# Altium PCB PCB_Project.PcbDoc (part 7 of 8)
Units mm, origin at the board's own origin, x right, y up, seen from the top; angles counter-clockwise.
Board outline 250 x 200 mm, 6 copper layers (Top Shielding/Sig, Sig 1, PWR, GND, Sig 4, Bottom Shielding/Sig), stack 1.568 mm thick; 736 components, 420 nets, 1929 pads, 2185 vias.
Unrouted connection lines stored in the file: 47.
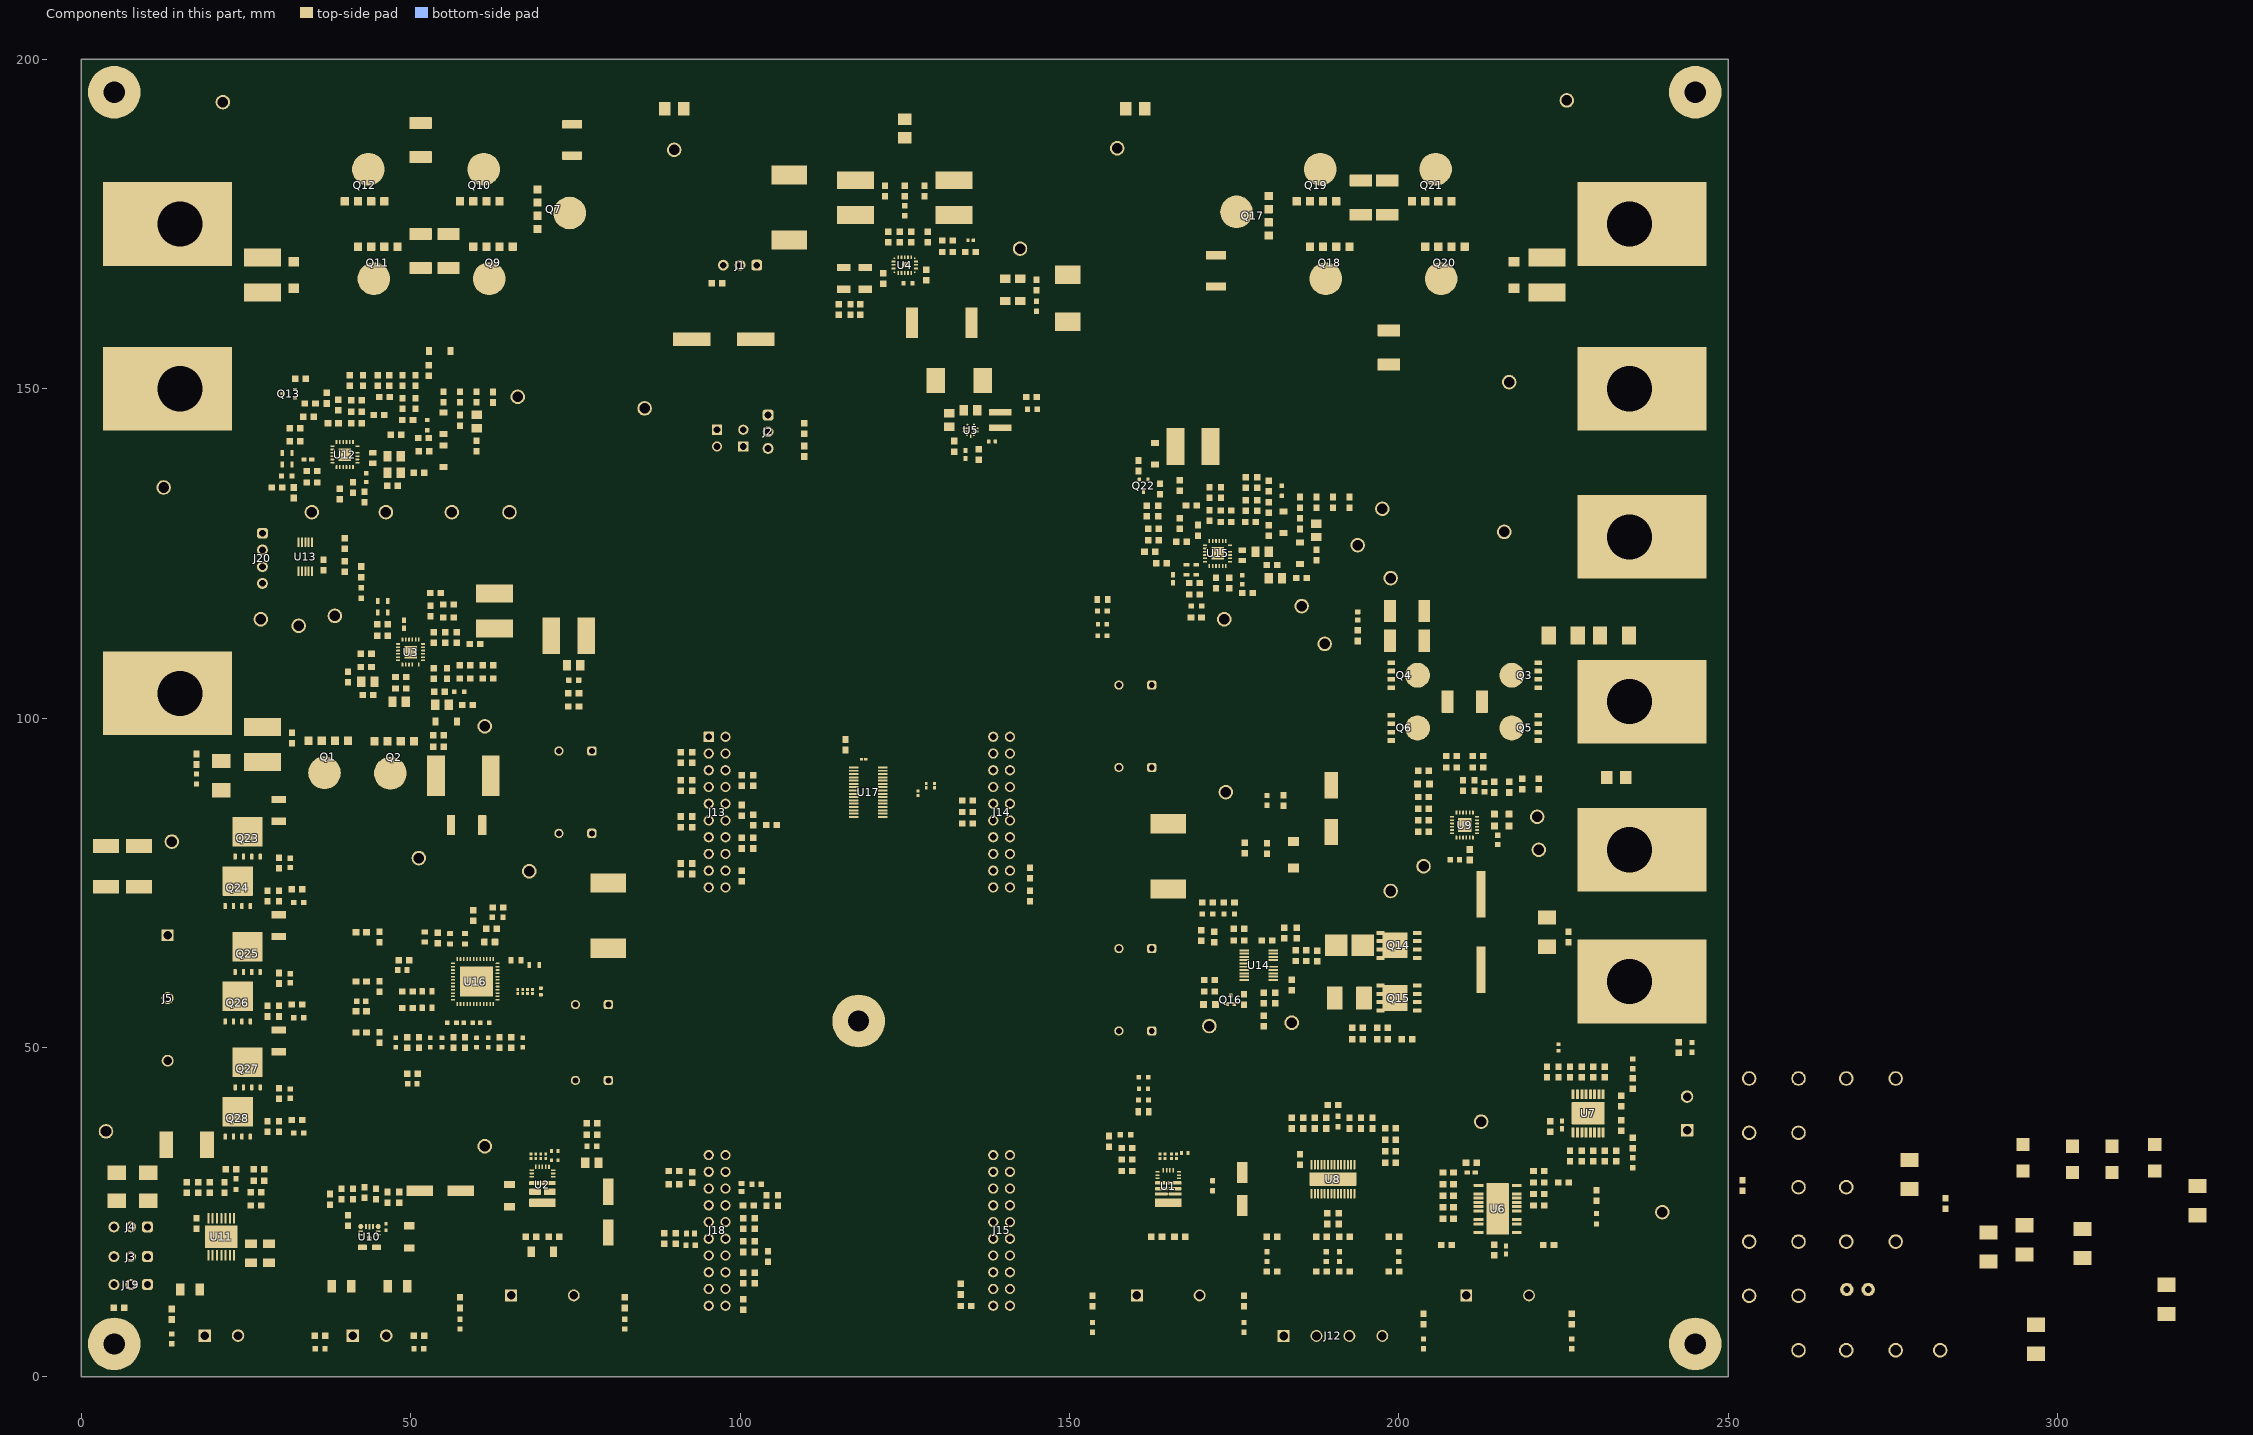
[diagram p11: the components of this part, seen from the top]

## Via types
v1: diameter 0.635, hole 0.254, Top Shielding/Sig to Bottom Shielding/Sig, tented both sides, 778 vias
v2: diameter 0.6, hole 0.254, Top Shielding/Sig to Bottom Shielding/Sig, tented both sides, 726 vias
v3: diameter 0.813, hole 0.406, Top Shielding/Sig to Bottom Shielding/Sig, 522 vias
v4: diameter 0.5, hole 0.2, Top Shielding/Sig to Bottom Shielding/Sig, tented both sides, 95 vias
v5: diameter 0.5, hole 0.2, Top Shielding/Sig to Bottom Shielding/Sig, 39 vias
v6: diameter 0.635, hole 0.254, Top Shielding/Sig to Bottom Shielding/Sig, 10 vias
v7: diameter 0.63, hole 0.33, Top Shielding/Sig to Bottom Shielding/Sig, tented both sides, 6 vias
v8: diameter 0.75, hole 0.254, Top Shielding/Sig to Bottom Shielding/Sig, tented both sides, 6 vias
v9: diameter 0.5, hole 0.2, Top Shielding/Sig to Bottom Shielding/Sig, tented top, 3 vias

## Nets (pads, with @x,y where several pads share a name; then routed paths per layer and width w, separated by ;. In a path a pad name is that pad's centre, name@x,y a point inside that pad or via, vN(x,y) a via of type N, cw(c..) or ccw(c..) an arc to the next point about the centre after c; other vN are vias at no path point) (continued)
pads on no net: H1.1 H2.1 H3.1 H4.1 H5.1 H6.0 H7.0 H8.0 H9.0 H10.0 J13.3 J13.4 J13.30 J14.16 J18.70 LBL1.0 Q23.9@23.8,81.37 Q23.9@23.8,83.15 Q23.9@25.25,81.37 Q23.9@25.25,82.3 Q23.9@25.25,83.15 Q23.9@26.7,81.37 Q23.9@26.7,83.15 Q24.9@22.3,73.87 Q24.9@22.3,75.65 Q24.9@23.75,73.87 Q24.9@23.75,74.8 Q24.9@23.75,75.65 Q24.9@25.2,73.87 Q24.9@25.2,75.65 Q25.9@23.8,63.87 Q25.9@23.8,65.65 Q25.9@25.25,63.87 Q25.9@25.25,64.8 Q25.9@25.25,65.65 Q25.9@26.7,63.87 Q25.9@26.7,65.65 Q26.9@22.3,56.37 Q26.9@22.3,58.15 Q26.9@23.75,56.37 Q26.9@23.75,57.3 Q26.9@23.75,58.15 Q26.9@25.2,56.37 Q26.9@25.2,58.15 Q27.9@23.8,46.37 Q27.9@23.8,48.15 Q27.9@25.25,46.37 Q27.9@25.25,47.3 Q27.9@25.25,48.15 Q27.9@26.7,46.37 Q27.9@26.7,48.15 Q28.9@22.3,38.87 Q28.9@22.3,40.65 Q28.9@23.75,38.87 Q28.9@23.75,39.8 Q28.9@23.75,40.65 Q28.9@25.2,38.87 Q28.9@25.2,40.65 SH-J1.0 SH-J2.0 SH-J3.0 SH-J4.0 U4.10 U4.12 U4.16 U4.18 U8.1 U8.14 U8.19 U8.24 U9.8 U9.17 U9.21 U9.25 U11.11 U16.31
copper on no net:
  other v4: 210,82.95 209.2,83.75 210,83.75 210.8,83.75 210,84.55

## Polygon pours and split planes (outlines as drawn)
SRC_U18_3 on Top Shielding/Sig "DRN_4 L1" (solid, shelved, pour order 381): 45 vertices, not listed, extent 185.875,171 208.625,179
48V_BAT2 on Top Shielding/Sig "48V_BAT2 L1" (solid, shelved, pour order 382): 17 vertices, not listed, extent 160.5,168.5 247,197.5
VS_ORing_1 on Top Shielding/Sig "VS_ORing L1" (solid, shelved, pour order 383): 90.5,193.75 91.75,195 158.25,195 159.5,193.75 159.5,191.25 158.25,190 91.75,190 90.5,191.25
48V on Top Shielding/Sig "48V L1" (solid, shelved, pour order 384): 76.75,73.25 74.994,75.006 74.994,164.994 81.5,171.5 81.5,176.75 88,176.75 100.25,189 126.25,189 126.25,180 106.25,180 87.5,161.25 87.5,77.5 83.25,73.25
48V_DRV8263 on Top Shielding/Sig "TOP_SHIELDING/SIG_NONET_P385" (solid, shelved, pour order 385): 17 vertices, not listed, extent 62.75,26 82.75,66.5
48V on Top Shielding/Sig "48V L1" (solid, shelved, pour order 386): 148.5,189 170,167.5 177.5,167.5 190,155 205,155 226,134 247,134 247,121 219,121 197.5,142.5 180,142.5 142.5,180 123.75,180 123.75,189
12V on Top Shielding/Sig "12V L1" (solid, shelved, pour order 387): 134.625,143.375 130.375,143.375 130,143.75 130,144.5 130.5,145 132.5,145 133.375,144.125 134.625,144.125 134.675,144.075 134.675,143.425
5V_BUCK on Top Shielding/Sig "5V_BUCK L1" (solid, shelved, pour order 388): 136.225,144.375 137.775,145.925 141.2,145.925 141.2,150.55 138.5,153.25 135.25,153.25 135.25,144.5 135.375,144.375
48V_BAT2 on Top Shielding/Sig "TOP_SHIELDING/SIG_NONET_P389" (solid, shelved, pour order 389): 183.875,186 185.875,186 185.875,187.5 185.875,186 187.875,186 187.875,187.5 187.875,186 189.875,186 189.875,187.5 189.875,186 191.125,186 191.125,188.5 183.875,188.5
48V_BAT2 on Top Shielding/Sig "TOP_SHIELDING/SIG_NONET_P390" (solid, shelved, pour order 390): 201.375,186 203.375,186 203.375,187.5 203.375,186 205.375,186 205.375,187.5 205.375,186 207.375,186 207.375,187.5 207.375,186 208.625,186 208.625,188.5 201.375,188.5
48V_Q22-24_3 on Top Shielding/Sig "TOP_SHIELDING/SIG_NONET_P391" (solid, shelved, pour order 391): 210.625,164 208.625,164 208.625,162.5 208.625,164 207.375,164 207.375,162.5 207.375,164 205.375,164 205.375,162.5 205.375,164 203.375,164 203.375,161.5 210.625,161.5
48V_BAT1 on Top Shielding/Sig "48V_BAT2 L1" (solid, shelved, pour order 394): 17 vertices, not listed, extent 3,168.5 89.5,197.5
SRC_U16_2 on Top Shielding/Sig "DRN_4 L1" (solid, shelved, pour order 396): 45 vertices, not listed, extent 41.375,171 70.25,179
48V on Top Shielding/Sig "TOP_SHIELDING/SIG_NONET_P399" (solid, shelved, pour order 399): 66.125,157.5 66.125,169.5 41.375,169.5 41.375,161.5 45.375,157.5
DRN_U16_2 on Top Shielding/Sig "TOP_SHIELDING/SIG_NONET_P400" (solid, shelved, pour order 400): 64.5,179.75 64.5,187.75 39,187.75 39,179.75
48V on Top Shielding/Sig "48V L1" (solid, shelved, pour order 402): 59.75,117.5 59.75,120.5 76,120.5 76,117.5
DRN_Q1_7 on Top Shielding/Sig "TOP_SHIELDING/SIG_NONET_P404" (solid, shelved, pour order 404): 17 vertices, not listed, extent 33.875,86.75 41.125,88
DRN_Q2_7 on Top Shielding/Sig "TOP_SHIELDING/SIG_NONET_P405" (solid, shelved, pour order 405): 17 vertices, not listed, extent 43.875,86.75 51.125,88
DRN_Q1_7 on Top Shielding/Sig "DRN_Q1 L1" (solid, shelved, pour order 406): 56.75,85.25 42.625,85.25 40.875,87 33.875,87 33.875,86.125 37.75,82.25 56.75,82.25
DRN_Q2_7 on Top Shielding/Sig "DRN_Q2 L1" (solid, shelved, pour order 407): 43.875,87.25 43.875,86.125 44.25,85.75 53.5,85.75 55.2,87.45 55.2,94.35 52.5,94.35 52.5,88 51.75,87.25
48V on Top Shielding/Sig "48V L1" (solid, shelved, pour order 408): 60.25,82.25 64.75,82.25 70,87.5 75.25,87.5 75.25,92.5 65.5,92.5 63.5,94.5 60.75,94.5 60.25,94
48V on Top Shielding/Sig "48V L1" (solid, shelved, pour order 409): 28 vertices, not listed, extent 22.75,45.25 72.5,88.75
DRV8363_OUTA on Top Shielding/Sig "DRV8363_OUTA L1" (solid, shelved, pour order 410): 26.15,72.9 26.15,78.25 18.25,78.25 10,70 10,66.25 11.25,65 15,65 20,70 20,71.5 21,72.5 25.75,72.5
DRV8363_OUTA on Top Shielding/Sig "TOP_SHIELDING/SIG_NONET_P411" (solid, shelved, pour order 411): 23.075,79.25 23.6,79.25 23.6,78.25 24.35,78.25 24.35,79.25 24.875,79.25 24.875,78.25 25.625,78.25 25.625,79.25 26.15,79.25 26.15,78 23.075,78
DRV8363_OUTB on Top Shielding/Sig "TOP_SHIELDING/SIG_NONET_P412" (solid, shelved, pour order 412): 23.075,61.75 23.6,61.75 23.6,60.75 24.35,60.75 24.35,61.75 24.875,61.75 24.875,60.75 25.625,60.75 25.625,61.75 26.15,61.75 26.15,60.5 23.075,60.5
DRV8363_OUTB on Top Shielding/Sig "DRV8363_OUTB L1" (solid, shelved, pour order 413): 25.75,55.25 26.15,55.65 26.15,60.75 10.75,60.75 10,60 10,55.75 10.5,55.25
12V on Top Shielding/Sig "12V L1" (solid, shelved, pour order 415): 21 vertices, not listed, extent 147.5,82.25 169,165
Cobra_Vout_14 on Top Shielding/Sig "Cobra_Vout_14 L1" (solid, shelved, pour order 416): 127.825,169.75 127.5,169.425 127.5,169.175 127.825,169.175 128,169 128.5,169 131.5,166 151,166 151,168 150,169 138.25,169 137.5,169.75
12V_IN on Top Shielding/Sig "12V_IN L1" (solid, shelved, pour order 417): 233.25,89.75 233.25,92 234.5,93.25 247,93.25 247,109 226,109 225.75,109.25 222.75,109.25 222,108.5 222,96 225,96 227,94 227,89.75
12V_IN on Top Shielding/Sig "TOP_SHIELDING/SIG_NONET_P418" (solid, shelved, pour order 418): 220.75,96.25 220.75,96.925 222,96.925 222,97.525 220.75,97.525 220.75,98.2 222,98.2 222,98.8 220.75,98.8 220.75,99.475 223,99.475 223,96.25
12V_IN on Top Shielding/Sig "TOP_SHIELDING/SIG_NONET_P419" (solid, shelved, pour order 419): 220.75,104.25 220.75,104.925 221.75,104.925 221.75,105.525 220.75,105.525 220.75,106.2 221.75,106.2 221.75,106.8 220.75,106.8 220.75,107.475 222.75,107.475 222.75,104.25
DRN_Q3_11 on Top Shielding/Sig "DRN_Q3 L1" (solid, shelved, pour order 420): 219.5,109 213,109 211.5,107.5 211.5,97.5 213,96 219.5,96 219.75,96.25 219.75,108.75
CS-_74900_11 on Top Shielding/Sig "CS-_74900_10 L1" (solid, shelved, pour order 421): 202.75,111.25 202.75,118 205,118 206.25,116.75 206.25,109.75 208.5,107.5 208.5,97.5 207,96 200.5,96 200.25,96.25 200.25,108.75
12V on Top Shielding/Sig "TOP_SHIELDING/SIG_NONET_P422" (solid, shelved, pour order 422): 198.5,108.75 198.5,108.075 198,108.075 198,107.475 198.5,107.475 198.5,106.8 198,106.8 198,106.2 198.5,106.2 198.5,105.525 197.75,105.525 197.75,108.75
12V on Top Shielding/Sig "TOP_SHIELDING/SIG_NONET_P423" (solid, shelved, pour order 423): 198.5,100.75 198.5,100.075 198,100.075 198,99.475 198.5,99.475 198.5,98.8 198,98.8 198,98.2 198.5,98.2 198.5,97.525 197.75,97.525 197.75,100.75
12V on Top Shielding/Sig "12V L1" (solid, shelved, pour order 424): 162.5,107.5 192.5,107.5 196.25,111.25 196.25,116.75 197.5,118 199.75,118 199.75,109.75 199.5,109.5 198.25,109.5 198,109.25 198,97.5 197.5,97 193,97 190,100 162.5,100
12V on Top Shielding/Sig "12V L1" (solid, shelved, pour order 425): 190.75,84.75 162.25,84.75 162.25,82.25 164,80.5 190.75,80.5
VOUT_TPS1211 on Top Shielding/Sig "VOUT_TPS1211 L1" (solid, shelved, pour order 426): 246.75,66.5 203.75,66.5 203.75,55.25 205.5,53.5 246.75,53.5
VOUT_TPS1211 on Top Shielding/Sig "TOP_SHIELDING/SIG_NONET_P427" (solid, shelved, pour order 427): 202.15,63.275 202.15,63.925 203.75,63.925 203.75,64.55 202.15,64.55 202.15,65.175 203.75,65.175 203.75,65.825 202.15,65.825 202.15,66.5 204,66.5 204,63.275
VOUT_TPS1211 on Top Shielding/Sig "VOUT_TPS1211 L1" (solid, shelved, pour order 428): 202.15,55.275 202.15,55.925 203.75,55.925 203.75,56.55 202.15,56.55 202.15,57.175 203.75,57.175 203.75,57.825 202.15,57.825 202.15,58.45 204,58.45 204,55.275
DRN_Q18_8 on Top Shielding/Sig "DRN_Q18 L1" (solid, shelved, pour order 429): 19 vertices, not listed, extent 194,63.275 197.75,67.725
DRN_Q19_8 on Top Shielding/Sig "DRN_Q19 L1" (solid, shelved, pour order 430): 19 vertices, not listed, extent 193.5,55.275 197.75,59.725
12V_DRV8245 on Top Shielding/Sig "12V_DRV8245 L1" (solid, shelved, pour order 431): 161.25,75.5 161.25,39.5 167.75,39.5 167.75,75.5
TPS1HTC30_OUT on Top Shielding/Sig "TPS1HTC30_OUT L1" (solid, shelved, pour order 432): 19,19.25 19,17.75 17.25,16 17.25,5.5 17.75,5 20.25,5 20.75,5.5 20.75,19.25
48V on Top Shielding/Sig "48V L1" (solid, shelved, pour order 433): 21.75,19.25 21.75,5.5 22.25,5 24.75,5 25.25,5.5 25.25,14.25 26,15 27.25,15 27.25,17.5 26.75,18 24.75,18 23.5,19.25
48V on Top Shielding/Sig "48V L1" (solid, shelved, pour order 436): 20 vertices, not listed, extent 24.75,15 45.5,42.5
TPS482H85_OUT1 on Top Shielding/Sig "TPS482H85_OUT1 L1" (solid, shelved, pour order 437): 42.05,20.05 40,18 40,5.5 40.25,5.25 42.25,5.25 42.5,5.5 42.5,17.5 43.4,18.4 43.4,20.05
TPS482H85_OUT2 on Top Shielding/Sig "TPS482H85_OUT2 L1" (solid, shelved, pour order 438): 45.45,20.05 47.5,18 47.5,5.5 47.25,5.25 45.25,5.25 45,5.5 45,17.5 44.1,18.4 44.1,20.05
DRV8263_OUT2 on Top Shielding/Sig "DRV8263_OUT2 L1" (solid, shelved, pour order 439): 17 vertices, not listed, extent 63.75,11 69.5,28.6
DRV8263_OUT1 on Top Shielding/Sig "DRV8263_OUT1 L1" (solid, shelved, pour order 440): 17 vertices, not listed, extent 70.5,11 76.25,28.6
VOUT2_TPS2HCS10 on Top Shielding/Sig "VOUT2_TPS2HCS10 L1" (solid, shelved, pour order 441): 229.5,42.125 229.5,44 229.75,44.25 244.5,44.25 245,43.75 245,41.75 244.5,41.25 235.25,41.25 234.375,42.125
VOUT1_TPS2HCS10 on Top Shielding/Sig "VOUT1_TPS2HCS10 L1" (solid, shelved, pour order 442): 229.5,37.875 229.5,36 229.75,35.75 244.5,35.75 245,36.25 245,38.25 244.5,38.75 235.25,38.75 234.375,37.875
12V on Top Shielding/Sig "12V L1" (solid, shelved, pour order 443): 231.25,41.75 222.25,41.75 221.75,41.25 221.75,38.75 222.25,38.25 231.25,38.25
12V on Top Shielding/Sig "12V L1" (solid, shelved, pour order 444): 211.25,28.75 211.25,33 218.75,33 218.75,28.75
12V on Top Shielding/Sig "12V L1" (solid, shelved, pour order 445): 211.25,20 211.25,22.25 218.75,22.25 218.75,20 218.25,19.5 211.75,19.5 218.25,19.5 211.75,19.5
VOUT2_TPS2HCS05 on Top Shielding/Sig "VOUT2_TPS2HCS05 L1" (solid, shelved, pour order 447): 217.15,23 217.15,24.075 217.25,24.175 219.825,24.175 222.5,21.5 222.5,12.5 220.75,10.75 218.75,10.75 217,12.5 217,17.75 219.25,20 219.25,22.25 218.6,22.9 217.25,22.9
12V on Top Shielding/Sig "12V L1" (solid, shelved, pour order 449): 189.1,28.5 189.1,26.2 188.65,25.75 188.65,24.3 191.35,24.3 191.35,25.75 190.9,26.2 190.9,28.5
OUT3_TPS4HC120 on Top Shielding/Sig "OUT3_TPS4HC120 L1" (solid, shelved, pour order 450): 188.4,28.5 187.6,28.5 187.6,26.6 185,24 185,5.75 185.75,5 188.25,5 189,5.75 189,14 187.95,15.05 187.95,25.45 188.4,25.9
OUT4_TPS4HC120 on Top Shielding/Sig "OUT4_TPS4HC120 L1" (solid, shelved, pour order 451): 186.6,28.5 187.4,28.5 187.4,26.65 184.5,23.75 184.5,5.75 183.75,5 181.75,5 181.05,5.7 181.05,22.05 186.6,27.6
OUT2_TPS4HC120 on Top Shielding/Sig "OUT2_TPS4HC120 L1" (solid, shelved, pour order 452): 191.6,28.5 192.4,28.5 192.4,26.6 195,24 195,5.75 194.25,5 191.75,5 191,5.75 191,14 192.05,15.05 192.05,25.45 191.6,25.9
OUT1_TPS4HC120 on Top Shielding/Sig "OUT1_TPS4HC120 L1" (solid, shelved, pour order 453): 193.4,28.5 192.6,28.5 192.6,26.65 195.5,23.75 195.5,5.75 196.25,5 198.25,5 198.95,5.7 198.95,22.05 193.4,27.6
DRV8245_OUT2 on Top Shielding/Sig "DRV8245_OUT2 L1" (solid, shelved, pour order 454): 164.85,28.8 160.05,28.8 157.5,26.25 157.5,13 159.25,11.25 161.25,11.25 163,13 163,24.5 162.25,25.25 162.25,27 162.75,27.5 164.85,27.5
DRV8245_OUT1 on Top Shielding/Sig "DRV8245_OUT1 L1" (solid, shelved, pour order 455): 165.15,28.8 169.95,28.8 172.5,26.25 172.5,13 170.75,11.25 168.75,11.25 167,13 167,24.5 167.75,25.25 167.75,27 167.25,27.5 165.15,27.5
12V_DRV8245 on Top Shielding/Sig "12V_DRV8245 L1" (solid, shelved, pour order 456): 165,47.25 167.75,47.25 177.25,37.75 177.25,29.5 176.95,29.2 163.1,29.2 163.1,29.7 168.95,29.7 171.75,32.5 171.75,35.5 167.75,39.5 165,39.5
12V on Top Shielding/Sig "12V L1" (solid, shelved, pour order 464): 134.625,143.375 130.375,143.375 130,143.75 130,144.5 130.5,145 132.5,145 133.375,144.125 134.625,144.125 134.675,144.075 134.675,143.425
48V_Q22-24_3 on Top Shielding/Sig "TOP_SHIELDING/SIG_NONET_P467" (solid, shelved, pour order 467): 193.125,164 191.875,164 191.875,162.5 191.875,164 189.875,164 189.875,162.5 189.875,164 187.875,164 187.875,162.5 187.875,164 185.875,164 185.875,161.5 193.125,161.5
48V_Q22-24_3 on Top Shielding/Sig "TOP_SHIELDING/SIG_NONET_P468" (solid, shelved, pour order 468): 189.875,157.5 185.875,161.5 185.875,162.5 210.625,162.5 210.625,161.5 206.625,157.5
48V_BAT2 on Top Shielding/Sig "TOP_SHIELDING/SIG_NONET_P469" (solid, shelved, pour order 469): 189.25,180.5 189.25,188 203.25,188 203.25,180.5
DRN_Q13_2 on Top Shielding/Sig "DRN_Q21 L1" (solid, shelved, pour order 471): 18 vertices, not listed, extent 71.375,173.25 78.625,178.5
DRN_U16_2 on Top Shielding/Sig "TOP_SHIELDING/SIG_NONET_P475" (solid, shelved, pour order 475): 17 vertices, not listed, extent 58.875,162 66.125,163.25
48V on Top Shielding/Sig "48V L1" (solid, shelved, pour order 478): 64.25,162.75 75.5,162.75 75.5,157.5 64.25,157.5
VOUT_TPS1214 on Top Shielding/Sig "TOP_SHIELDING/SIG_NONET_P480" (solid, shelved, pour order 480): 30 vertices, not listed, extent 3.25,96 49.125,110.25
DRV8363_OUTC on Top Shielding/Sig "TOP_SHIELDING/SIG_NONET_P486" (solid, shelved, pour order 486): 23.075,44.25 23.6,44.25 23.6,43.25 24.35,43.25 24.35,44.25 24.875,44.25 24.875,43.25 25.625,43.25 25.625,44.25 26.15,44.25 26.15,43 23.075,43
DRV8363_OUTC on Top Shielding/Sig "DRV8363_OUTC L1" (solid, shelved, pour order 488): 26.15,43.25 26.15,37.9 26,37.75 17.25,37.75 10,45 10,48.75 11.25,50 15,50 21.75,43.25
48V on Top Shielding/Sig "48V L1" (solid, shelved, pour order 501): 18 vertices, not listed, extent 36,19 60,50
VOUT1_TPS2HCS05 on Top Shielding/Sig "VOUT1_TPS2HCS05 L1" (solid, shelved, pour order 509): 212.85,23 212.85,24.075 212.75,24.175 210.175,24.175 207.5,21.5 207.5,12.5 209.25,10.75 211.25,10.75 213,12.5 213,17.75 210.75,20 210.75,22.25 211.4,22.9 212.75,22.9
SW_U5_14 on Top Shielding/Sig "SW_U5_14 L1" (solid, shelved, pour order 522): 135.375,144.125 136.5,144.125 136.925,144.55 141.15,144.55 141.15,143.575 136.8,143.575 136.5,143.875 135.375,143.875
12V on Top Shielding/Sig "12V L1" (solid, remove dead copper, shelved, pour order 524): 189.1,55.775 189.1,63.4 188.75,63.75 188.75,79.25 187.5,80.5 187.5,81.575 189.675,81.575 192.25,79 192.2,63.85 191.5,63.15 191.475,55.775
12V_IN on Top Shielding/Sig "12V_IN L1" (solid, shelved, pour order 526): 233.75,114 233.75,99 236.25,99 236.25,114
VIN_Cobra_14 on Top Shielding/Sig "VIN_Cobra_14 L1" (solid, shelved, pour order 527): 123.625,167.875 123,167.875 122.125,167 121.25,167 120,165.75 114.75,165.75 110.25,170.25 110.25,174 104.75,174 104.75,170.25 110.875,164.125 114.25,164.125 114.25,162.25 119.75,162.25 123.625,166.125
Cobra_Vout_14 on Top Shielding/Sig "Cobra_Vout_14 L1" (solid, shelved, pour order 529): 134.125,157.625 134.125,167.375 136.125,167.375 136.125,157.625
SW_U4_14 on Top Shielding/Sig "SW_U4_14 L1" (solid, shelved, pour order 531): 125.125,167.875 124.375,167.875 124.375,163.125 125.125,162.375 125.125,157.625 127.125,157.625 127.125,163.75 125.125,165.75
VIN_Cobra_14 on Top Shielding/Sig "VIN_Cobra_14 L1" (solid, shelved, pour order 533): 126.375,167.875 127,167.875 127.875,167 128.75,167 128.75,165.875 127.375,165.875 126.375,166.875
NetD24_2 on Top Shielding/Sig "TOP_SHIELDING/SIG_NONET_P535" (solid, shelved, pour order 535): 233.5,92 233.5,86.75 226.75,86.75 226.75,73.25 247,73.25 247,86.75 247,92
DRN_Q13_2 on Top Shielding/Sig "TOP_SHIELDING/SIG_NONET_P539" (solid, shelved, pour order 539): 70.913,188.062 70.913,173.087 70.913,171.25 80.25,171.25 80.25,188
DRN_Q13_2 on Top Shielding/Sig "TOP_SHIELDING/SIG_NONET_P540" (solid, shelved, pour order 540): 80,188 86.75,188 86.75,178.5 80.25,178.5
SRC_U18_3 on Top Shielding/Sig "TOP_SHIELDING/SIG_NONET_P547" (solid, shelved, pour order 547): 18 vertices, not listed, extent 179.25,172.75 186,180.25
DRN_Q21_3 on Top Shielding/Sig "TOP_SHIELDING/SIG_NONET_P549" (solid, shelved, pour order 549): 178.25,168.5 170.75,168.5 159.75,179.5 159.75,184.25 162.5,185 163.25,187.5 169.75,187.5 171,186.25 178.25,186.25
DRN_U16_2 on Top Shielding/Sig "TOP_SHIELDING/SIG_NONET_P551" (solid, shelved, pour order 551): 39.276,187.75 38.026,187.75 36.026,185.75 36.026,179.75 39.276,179.75
DRN_U16_2 on Top Shielding/Sig "TOP_SHIELDING/SIG_NONET_P554" (solid, shelved, pour order 554): 64.25,187.75 67.25,187.75 68,187 68,179.75 64.25,179.75
GND on Top Shielding/Sig "GND L1" (solid, shelved, pour order 556): 0.5,2.5 0.5,197.5 2.5,199.5 247.5,199.5 249.5,197.5 249.5,2.5 247.5,0.5 2.5,0.5
48V_Q22-24_3 on Bottom Shielding/Sig "BOTTOM_SHIELDING/SIG_NONET_P392" (solid, shelved, pour order 392): 189.875,157.5 185.875,161.5 185.875,162.5 210.625,162.5 210.625,161.5 206.625,157.5
48V_BAT2 on Bottom Shielding/Sig "BOTTOM_SHIELDING/SIG_NONET_P393" (solid, shelved, pour order 393): 190.25,180.5 190.25,188 203.25,188 203.25,180.5
48V on Bottom Shielding/Sig "48V L1" (solid, shelved, pour order 401): 65,162.75 75.5,162.75 75.5,157.5 65,157.5
VOUT_TPS1214 on Bottom Shielding/Sig "BOTTOM_SHIELDING/SIG_NONET_P403" (solid, shelved, pour order 403): 30 vertices, not listed, extent 3.25,96.75 49.125,110.25
DRV8363_OUTC on Bottom Shielding/Sig "DRV8363_OUTC L1" (solid, shelved, pour order 414): 26.15,43.25 26.15,42.4 21.5,37.75 17.25,37.75 10,45 10,48.75 11.25,50 15,50 21.75,43.25
48V on Bottom Shielding/Sig "48V L1" (solid, shelved, pour order 435): 18 vertices, not listed, extent 36,19 60,50
VOUT1_TPS2HCS05 on Bottom Shielding/Sig "VOUT1_TPS2HCS05 L1" (solid, shelved, pour order 446): 211.25,22.75 211.25,24.175 210.175,24.175 207.5,21.5 207.5,12.5 209.25,10.75 211.25,10.75 213,12.5 213,17.75 210.75,20 210.75,22.25
SRC_U18_3 on Bottom Shielding/Sig "DRN_4 L1" (solid, shelved, pour order 458): 45 vertices, not listed, extent 185.875,171.75 208.625,179
48V_BAT2 on Bottom Shielding/Sig "48V_BAT2 L1" (solid, shelved, pour order 459): 17 vertices, not listed, extent 160.5,168.5 247,197.5
VS_ORing_1 on Bottom Shielding/Sig "VS_ORing L1" (solid, shelved, pour order 460): 90.5,193.75 91.75,195 158.25,195 159.5,193.75 159.5,191.25 158.25,190 91.75,190 90.5,191.25
48V on Bottom Shielding/Sig "48V L1" (solid, shelved, pour order 461): 17 vertices, not listed, extent 74.994,73.25 126.25,189
48V_DRV8263 on Bottom Shielding/Sig "BOTTOM_SHIELDING/SIG_NONET_P462" (solid, shelved, pour order 462): 17 vertices, not listed, extent 62.75,26 82.75,63.75
48V on Bottom Shielding/Sig "48V L1" (solid, shelved, pour order 463): 148.5,189 170,167.5 177.5,167.5 190,155 205,155 226,134 247,134 247,121 219,121 197.5,142.5 180,142.5 142.5,180 123.75,180 123.75,189
5V_BUCK on Bottom Shielding/Sig "5V_BUCK L1" (solid, shelved, pour order 465): 136.225,144.375 137.775,145.925 141.2,145.925 141.2,146.925 137.625,150.5 135.25,150.5 135.25,144.5 135.375,144.375
48V_BAT1 on Bottom Shielding/Sig "48V_BAT2 L1" (solid, shelved, pour order 470): 17 vertices, not listed, extent 3,168.5 89.5,197.5
48V_BAT2 on Bottom Shielding/Sig "BOTTOM_SHIELDING/SIG_NONET_P472" (solid, shelved, pour order 472): 184,188.5 184,180.25 191.5,180.25 191.5,188.5
48V_BAT2 on Bottom Shielding/Sig "BOTTOM_SHIELDING/SIG_NONET_P476" (solid, shelved, pour order 476): 201.5,188.5 201.5,180.25 209,180.25 209,188.5
SRC_U16_2 on Bottom Shielding/Sig "DRN_4 L1" (solid, shelved, pour order 477): 45 vertices, not listed, extent 41.375,171 70.25,179
48V on Bottom Shielding/Sig "BOTTOM_SHIELDING/SIG_NONET_P479" (solid, shelved, pour order 479): 66.336,157.25 66.336,160.25 66.336,169.25 41.375,169.25 41.375,161.5 45.375,157.5
DRN_U16_2 on Bottom Shielding/Sig "BOTTOM_SHIELDING/SIG_NONET_P481" (solid, shelved, pour order 481): 64.5,179.75 64.5,187.75 39,187.75 39,179.75
48V on Bottom Shielding/Sig "48V L1" (solid, shelved, pour order 482): 65,117.5 65,120.5 76,120.5 76,117.5
DRN_Q1_7 on Bottom Shielding/Sig "DRN_Q1 L1" (solid, shelved, pour order 483): 55.25,85.25 42.625,85.25 40.875,87 33.875,87 33.875,86.125 37.75,82.25 55.25,82.25
DRN_Q2_7 on Bottom Shielding/Sig "DRN_Q2 L1" (solid, shelved, pour order 484): 43.875,87.25 43.875,86.125 44.25,85.75 53.5,85.75 54.5,86.75 54.5,88.5 52.5,88.5 52.5,88 51.75,87.25
48V on Bottom Shielding/Sig "48V L1" (solid, shelved, pour order 485): 60.25,82.25 64.75,82.25 70,87.5 75.25,87.5 75.25,92.5 65.5,92.5 64.75,93.25 61.5,93.25 60.25,92
48V on Bottom Shielding/Sig "48V L1" (solid, shelved, pour order 487): 27 vertices, not listed, extent 27.5,45.25 72.5,88.75
DRV8363_OUTA on Bottom Shielding/Sig "DRV8363_OUTA L1" (solid, shelved, pour order 489): 26.15,77.4 26.15,78.25 18.25,78.25 10,70 10,66.25 11.25,65 15,65 20,70 20,71.25
DRV8363_OUTB on Bottom Shielding/Sig "DRV8363_OUTB L1" (solid, shelved, pour order 490): 21.75,55.25 26.15,59.65 26.15,60.75 10.75,60.75 10,60 10,55.75 10.5,55.25
12V on Bottom Shielding/Sig "12V L1" (solid, shelved, pour order 491): 21 vertices, not listed, extent 147.5,82.25 169,165
Cobra_Vout_14 on Bottom Shielding/Sig "Cobra_Vout_14 L1" (solid, shelved, pour order 492): 128,169.75 127.75,169.5 127.75,169 128.5,169 131.5,166 151,166 151,168 150,169 138.25,169 137.5,169.75
12V_IN on Bottom Shielding/Sig "12V_IN L1" (solid, shelved, pour order 493): 222,96 225,96 227,94 227,89.5 247,89.5 247,109 226,109 225.75,109.25 222.75,109.25 222,108.5
DRN_Q3_11 on Bottom Shielding/Sig "DRN_Q3 L1" (solid, shelved, pour order 494): 219.5,109 213,109 211.5,107.5 211.5,97.5 213,96 219.5,96 219.75,96.25 219.75,108.75
CS-_74900_11 on Bottom Shielding/Sig "CS-_74900_10 L1" (solid, shelved, pour order 495): 202.75,111.25 202.75,118 205,118 206.25,116.75 206.25,109.75 208.5,107.5 208.5,97.5 207,96 205,96 200.25,100.75 200.25,108.75
12V on Bottom Shielding/Sig "12V L1" (solid, shelved, pour order 496): 162.5,107.5 192.5,107.5 196.25,111.25 196.25,116.75 197.5,118 199.75,118 199.75,109.75 199.5,109.5 198.25,109.5 198,109.25 198,97.5 197.5,97 193,97 190,100 162.5,100
12V on Bottom Shielding/Sig "12V L1" (solid, shelved, pour order 497): 189,84.75 162.25,84.75 162.25,82.25 163.75,80.75 189,80.75
VOUT_TPS1211 on Bottom Shielding/Sig "VOUT_TPS1211 L1" (solid, shelved, pour order 498): 246.75,66.5 203.75,66.5 203.75,55.25 205.5,53.5 246.75,53.5
12V_DRV8245 on Bottom Shielding/Sig "12V_DRV8245 L1" (solid, shelved, pour order 499): 161.25,75.5 161.25,39.5 167.75,39.5 167.75,75.5
TPS1HTC30_OUT on Bottom Shielding/Sig "TPS1HTC30_OUT L1" (solid, shelved, pour order 502): 18.75,17.5 17.25,16 17.25,5.5 17.75,5 20.25,5 20.75,5.5 20.75,17.5
48V on Bottom Shielding/Sig "48V L1" (solid, shelved, pour order 503): 21.75,17.5 21.75,5.5 22.25,5 24.75,5 25.25,5.5 25.25,14.25 26,15 27.25,15 27.25,17.5 26.75,18 24.75,18 24.25,17.5
48V on Bottom Shielding/Sig "48V L1" (solid, shelved, pour order 504): 20 vertices, not listed, extent 24.75,15 45.5,42.5
TPS482H85_OUT1 on Bottom Shielding/Sig "TPS482H85_OUT1 L1" (solid, shelved, pour order 505): 42.05,20.05 40,18 40,5.5 40.25,5.25 42.25,5.25 42.5,5.5 42.5,17.5 43.4,18.4 43.4,20.05
TPS482H85_OUT2 on Bottom Shielding/Sig "TPS482H85_OUT2 L1" (solid, shelved, pour order 506): 45.45,20.05 47.5,18 47.5,5.5 47.25,5.25 45.25,5.25 45,5.5 45,17.5 44.1,18.4 44.1,20.05
DRV8263_OUT2 on Bottom Shielding/Sig "DRV8263_OUT2 L1" (solid, shelved, pour order 507): 19 vertices, not listed, extent 63.75,11 69.75,28.6
DRV8263_OUT1 on Bottom Shielding/Sig "DRV8263_OUT1 L1" (solid, shelved, pour order 508): 19 vertices, not listed, extent 70.25,11 76.25,28.6
VOUT2_TPS2HCS10 on Bottom Shielding/Sig "VOUT2_TPS2HCS10 L1" (solid, shelved, pour order 510): 231.75,42.25 231.5,42.5 231.5,43.5 232.25,44.25 244.5,44.25 245,43.75 245,41.75 244.5,41.25 235.25,41.25 234.25,42.25
VOUT1_TPS2HCS10 on Bottom Shielding/Sig "VOUT1_TPS2HCS10 L1" (solid, shelved, pour order 512): 231.75,37.75 231.5,37.5 231.5,36.5 232.25,35.75 244.5,35.75 245,36.25 245,38.25 244.5,38.75 235.25,38.75 234.25,37.75
VOUT2_TPS2HCS05 on Bottom Shielding/Sig "VOUT2_TPS2HCS05 L1" (solid, shelved, pour order 513): 218.75,22.75 218.75,24.175 219.825,24.175 222.5,21.5 222.5,12.5 220.75,10.75 218.75,10.75 217,12.5 217,17.75 219.25,20 219.25,22.25
OUT3_TPS4HC120 on Bottom Shielding/Sig "OUT3_TPS4HC120 L1" (solid, shelved, pour order 514): 188.4,27.25 187.6,27.25 187.6,26.6 185,24 185,5.75 185.75,5 188.25,5 189,5.75 189,14 187.95,15.05 187.95,25.45 188.4,25.9
OUT4_TPS4HC120 on Bottom Shielding/Sig "OUT4_TPS4HC120 L1" (solid, shelved, pour order 515): 186.25,27.25 187.4,27.25 187.4,26.65 184.5,23.75 184.5,5.75 183.75,5 181.75,5 181.05,5.7 181.05,22.05
OUT2_TPS4HC120 on Bottom Shielding/Sig "OUT2_TPS4HC120 L1" (solid, shelved, pour order 516): 191.6,27.25 192.4,27.25 192.4,26.6 195,24 195,5.75 194.25,5 191.75,5 191,5.75 191,14 192.05,15.05 192.05,25.45 191.6,25.9
OUT1_TPS4HC120 on Bottom Shielding/Sig "OUT1_TPS4HC120 L1" (solid, shelved, pour order 517): 193.75,27.25 192.6,27.25 192.6,26.65 195.5,23.75 195.5,5.75 196.25,5 198.25,5 198.95,5.7 198.95,22.05
DRV8245_OUT2 on Bottom Shielding/Sig "DRV8245_OUT2 L1" (solid, shelved, pour order 518): 164.85,28.8 160.05,28.8 157.5,26.25 157.5,13 159.25,11.25 161.25,11.25 163,13 163,24.5 162.25,25.25 162.25,27 162.75,27.5 164.85,27.5
DRV8245_OUT1 on Bottom Shielding/Sig "DRV8245_OUT1 L1" (solid, shelved, pour order 520): 165.15,28.8 169.95,28.8 172.5,26.25 172.5,13 170.75,11.25 168.75,11.25 167,13 167,24.5 167.75,25.25 167.75,27 167.25,27.5 165.15,27.5
12V_DRV8245 on Bottom Shielding/Sig "12V_DRV8245 L1" (solid, shelved, pour order 521): 165,47.25 167.75,47.25 175,40 175,31.25 172.95,29.2 163.1,29.2 163.1,29.7 168.95,29.7 171.75,32.5 171.75,35.5 167.75,39.5 165,39.5
12V on Bottom Shielding/Sig "12V L6" (solid, shelved, pour order 523): 33 vertices, not listed, extent 176.25,19.75 231,84.75
12V on Bottom Shielding/Sig "12V L6" (solid, shelved, pour order 525): 21 vertices, not listed, extent 188.75,25 201.25,45
DRN_Q18_8 on Bottom Shielding/Sig "DRN_Q18_8 L6" (solid, shelved, pour order 534): 197.5,67.5 201.5,67.5 201.5,63.5 197.5,63.5
DRN_Q19_8 on Bottom Shielding/Sig "DRN_Q19_8 L6" (solid, shelved, pour order 537): 197.5,59.5 201.5,59.5 201.5,55.5 197.5,55.5
NetD24_2 on Bottom Shielding/Sig "BOTTOM_SHIELDING/SIG_NONET_P542" (solid, shelved, pour order 542): 233,92.25 233,86.75 227,86.75 227,73.25 247,73.25 247,86.75 246.75,87 246.75,92.25
DRN_Q13_2 on Bottom Shielding/Sig "BOTTOM_SHIELDING/SIG_NONET_P543" (solid, shelved, pour order 543): 70.791,188.045 80.455,188.045 80.5,188 80.5,171.25 70.746,171.25
48V_Q22-24_3 on Bottom Shielding/Sig "BOTTOM_SHIELDING/SIG_NONET_P544" (solid, shelved, pour order 544): 186,169.75 186,161.5 193.25,161.5 193.25,169.75
48V_Q22-24_3 on Bottom Shielding/Sig "BOTTOM_SHIELDING/SIG_NONET_P545" (solid, shelved, pour order 545): 203.5,162 203.5,169.5 210.5,169.5 210.5,162
DRN_Q13_2 on Bottom Shielding/Sig "BOTTOM_SHIELDING/SIG_NONET_P546" (solid, shelved, pour order 546): 80,188 86.75,188 86.75,178 80.25,178
SRC_U18_3 on Bottom Shielding/Sig "BOTTOM_SHIELDING/SIG_NONET_P548" (solid, shelved, pour order 548): 18 vertices, not listed, extent 179.25,172.75 186,180.25
DRN_Q21_3 on Bottom Shielding/Sig "BOTTOM_SHIELDING/SIG_NONET_P550" (solid, shelved, pour order 550): 178.5,168.25 171,168.25 160,179.25 160,184 162.5,185 163.5,187.25 170,187.25 171.25,186 178.5,186
DRN_U16_2 on Bottom Shielding/Sig "BOTTOM_SHIELDING/SIG_NONET_P552" (solid, shelved, pour order 552): 39.25,187.75 38,187.75 36,185.75 36,179.75 39.25,179.75
DRN_U16_2 on Bottom Shielding/Sig "BOTTOM_SHIELDING/SIG_NONET_P553" (solid, shelved, pour order 553): 64.25,187.75 67.25,187.75 68,187 68,179.75 64.25,179.75
GND on Bottom Shielding/Sig "GND L6" (solid, shelved, pour order 555): 0.5,2.5 0.5,197.5 2.5,199.5 247.5,199.5 249.5,197.5 249.5,2.5 247.5,0.5 2.5,0.5
3V3 on PWR "3V3 L3" (solid, remove dead copper, shelved, pour order 519): 37 vertices, not listed, extent 15,9.5 237.5,195
GND on PWR "GND L3" (solid, shelved, pour order 528): 0.5,2.5 0.5,197.5 2.5,199.5 247.5,199.5 249.5,197.5 249.5,2.5 247.5,0.5 2.5,0.5
GND on Sig 4 "GND L5" (solid, shelved, pour order 536): 0.5,2.5 0.5,197.5 2.5,199.5 247.5,199.5 249.5,197.5 249.5,2.5 247.5,0.5 2.5,0.5
GND on GND "GND L4" (solid, shelved, pour order 532): 0.5,2.5 0.5,197.5 2.5,199.5 247.5,199.5 249.5,197.5 249.5,2.5 247.5,0.5 2.5,0.5
GND on Sig 1 "GND L2" (solid, shelved, pour order 530): 0.5,2.5 0.5,197.5 2.5,199.5 247.5,199.5 249.5,197.5 249.5,2.5 247.5,0.5 2.5,0.5

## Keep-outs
Top Shielding/Sig:
  rectangle: 208.625,84.875 208.75,85.125
Keep-Out Layer:
  text ".Layer_Name" at 10.656,-21.806 h1.52

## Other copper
Top Shielding/Sig:
  rectangle net GND: 227.25,143.75 246.25,156.25
  rectangle net GND: 4,143.75 22.75,156.25
  pour cut-out: 64.5,171 64.5,172.75 68,172.75 68,171
  text ".Layer_Name" at 10.656,-21.806 h1.52
Bottom Shielding/Sig:
  text ".Layer_Name" at 10.656,-21.806 h1.52

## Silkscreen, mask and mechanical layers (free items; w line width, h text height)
Top Overlay:
  lines w0.25: 48,46.5 48,47 48.25,47.25 ; 48.5,116 50.5,116 51.5,115.5 51.5,114.5 52.25,114 ; 59.25,48.75 59.5,48.5 59.5,45.75 62,45.75 ; 129.5,147.25 130,147.75 130.75,147.75 132.75,147.75 ; 133.5,172 133.75,173 ; 177.625,67 179,68.75 ; 181.5,132.75 183,132.75 183.5,133.25 183.5,138.5 187.25,138.5 ; 210,96.5 210,93.5 210.15,93.35 ; 213,87.75 213,88 ; 222.5,86.75 223.5,87.5
  lines w0.305: 88.9,0 88.9,18.415 ; 88.9,23.495 88.9,27.94 ; 88.9,35.56 88.9,95.25 ; 88.9,99.06 88.9,137.795 147.32,137.795 147.32,99.06 ; 147.32,0 147.32,31.75 ; 147.32,35.56 147.32,95.25
  text "+" at 107.29,156.866 h3 r90
  text "'.PRJ_Number'.PCB_Rev" at 161,154.25 h2.75
  text "48V Zone Reference Design" at 161,151.25 h3
  text "GATE" at 68.75,149.86 h2.75
  text "TPS1212" at 68.75,147.61 h2.75
  text "Input1" at 68.75,145.11 h2.75
  text "AM263P4-LP Connectors" at 107.701,129.71 h3.05
  text "I2t" at 196,127.269 h2.25
  text "TPS1212" at 196,125.504 h2.25
  text "Input2" at 196,123.326 h2.25
  text "G_TPS1212" at 179.962,112.72 h1.25
  text "Input2" at 182.006,111.47 h1.25
  text "G_TPS1214" at 16.202,111.11 h1
  text "IMON" at 170.502,110.47 h2
  text "TPS1212" at 168.462,108.72 h2
  text "Input2" at 170.256,107.22 h2
  text "HGATE" at 184.677,106.72 h2.75
  text "LM74900" at 183.712,104.72 h2.75
  text "GATE" at 63.03,96.22 h2.5
  text "VOUT" at 3.5,94.72 h3
  text "TPS1214" at 59.207,94.22 h2.5
  text "12V_OFF_BOARD" at 226.553,93.47 h2.75
  text "TPS1214" at 3.498,92.47 h3
  text "DCDC" at 238.462,90.97 h2.75
  text "+" at 189.116,78.46 h3
  text "GATE" at 190.03,74.72 h2.75
  text "TPS1211" at 186.462,72.47 h2.75
  text "+" at 211.866,56.21 h3
  text "VOUT" at 218.857,55.86 h3
  text "TPS1211" at 215.611,53.61 h3
  text "G" at 182.002,49.22 h2.75
  text "12V" at 169.502,48.72 h2.75
  text "TPS1211" at 179.962,47.22 h2.75
  text "DRV8245" at 167.309,46.72 h2.75
  text "+" at 176.884,34.79 h3 r180
  text "+" at 82.134,31.79 h3 r180
  text "+" at 61.79,27.616 h3 r90
  text ".Layer_Name" at 10.656,-21.806 h1.52
Bottom Overlay:
  text ".Layer_Name" at 10.656,-21.806 h1.52
Top Paste:
  text ".Layer_Name" at 10.656,-21.806 h1.52
Bottom Paste:
  text ".Layer_Name" at 10.656,-21.806 h1.52
Top Solder:
  text ".Layer_Name" at 10.656,-21.806 h1.52
  text ".Layer_Name" at 10.656,-21.806 h1.52
Bottom Solder:
  text ".Layer_Name" at 10.656,-21.806 h1.52
Drill Guide:
  text ".Layer_Name" at 306.5,101.5 h1.52
  text ".Layer_Name" at 10.656,-21.806 h1.52
M1 Board Outline:
  the board outline again, w0.254
  text ".Layer_Name" at 10.656,-21.806 h1.52
M2 Board Dimensions:
  rectangle: 0,-6.485 3.175,-3.31
  rectangle: 3.175,-9.66 12.7,-6.485
  lines w0.178: 0,-6.485 25.4,-6.485 ; 3.175,-9.66 3.175,-3.31 ; 6.35,-9.66 6.35,-3.31 ; 12.7,-9.66 12.7,-3.31 ; 19.05,-9.66 19.05,-3.31 ; 0,-9.66 25.4,-9.66 25.4,-3.31 0,-3.31 0,-9.66
  text ".Layer_Name" at 10.656,-21.806 h1.52
M3 3D STEP Top:
  text ".Layer_Name" at 10.656,-21.806 h1.52
M4 3D STEP Bottom:
  text ".Layer_Name" at 10.656,-21.806 h1.52
M5 Assembly Top:
  lines w0.254: -11.417,-23.626 156.223,-23.626 ; -11.417,-18.462 156.274,-18.462 ; -11.417,-13.297 -11.417,-28.791 90.31,-28.791 156.274,-28.791 156.274,-13.297 -11.404,-13.297 -11.404,-28.791 28.614,-28.791 ; 51.194,-28.791 51.194,-13.297 ; 83.376,-18.462 83.376,-13.297 ; 104.712,-18.462 104.712,-13.297 ; 120.511,-28.956 120.511,-23.804
  text "COMPONENTS MARKED 'DNP' SHOULD NOT BE POPULATED." at 32.799,-8.09 h1.52
  text "ASSEMBLY VARIANT:" at 32.786,-11.024 h1.52
  text ".VariantName" at 59.101,-11.024 h1.52
  text "PCB VIEWED FROM TOP SIDE" at -9.804,-16.654 h1.52
  text "BOARD #:" at 53.099,-16.654 h1.52
  text ".PRJ_Number" at 66.955,-16.654 h1.52
  text "REV:" at 88.405,-16.654 h1.52
  text ".PCB_Rev" at 95.809,-16.654 h1.52
  text "SVN REV:" at 109.69,-16.654 h1.52
  text ".VersionControl_RevNumber" at 169.543,-17.154 h1.52
  text "TID #:" at 53.099,-21.819 h1.52
  text ".TID" at 66.955,-21.819 h1.52
  text "PLOT NAME =" at -9.804,-27.034 h1.52
  text ".plot_File_Name" at 10.656,-27.034 h1.52
  text "GENERATED    :" at 53.15,-27.034 h1.52
  text ".Print_Date" at 75.235,-27.034 h1.52
  text ".Print_Time" at 93.752,-27.034 h1.52
  text "TEXAS INSTRUMENTS" at 125.87,-27.034 h1.52
M6 Assembly Bottom:
  lines w0.254: -11.429,-18.474 156.261,-18.474 ; -11.379,-23.639 156.261,-23.639 ; 24.334,-28.969 24.334,-23.817 ; 40.133,-18.474 40.133,-13.31 ; 61.469,-18.474 61.469,-13.31 ; 93.65,-28.804 93.65,-13.31 ; 116.231,-28.804 156.249,-28.804 156.249,-13.31 -11.429,-13.31 -11.429,-28.804 54.534,-28.804 156.261,-28.804 156.261,-13.31
  text "ASSEMBLY VARIANT:" at 172.215,-12 h1.52
  text ".VariantName" at 111,-12.25 h1.52
  text ".VersionControl_RevNumber" at 22.302,-16.667 h1.52
  text "SVN REV:" at 35.154,-16.667 h1.52
  text ".PCB_Rev" at 49.035,-16.667 h1.52
  text "REV:" at 56.439,-16.667 h1.52
  text ".PRJ_Number" at 77.89,-16.667 h1.52
  text "BOARD #:" at 91.745,-16.667 h1.52
  text "PCB VIEWED FROM BOTTOM SIDE" at 154.648,-16.667 h1.52
  text ".TID" at 77.89,-21.831 h1.52
  text "TID #:" at 91.745,-21.831 h1.52
  text "TEXAS INSTRUMENTS" at 18.974,-27.047 h1.52
  text ".Print_Time" at 51.093,-27.047 h1.52
  text ".Print_Date" at 69.609,-27.047 h1.52
  text "GENERATED    :" at 91.695,-27.047 h1.52
  text ".plot_File_Name" at 134.189,-27.047 h1.52
  text "PLOT NAME =" at 154.648,-27.047 h1.52
M9 Title Sheet:
  drawing of 58 lines, arcs and shapes, not listed
  text "1" at 14.792,204.127 h1.78
  text "2" at 78.182,204.127 h1.78
  text "3" at 141.411,204.127 h1.78
  text "4" at 205.08,204.127 h1.78
  text "5" at 268.555,204.127 h1.78
  text "6" at 332.182,204.127 h1.78
  text "A" at -14.579,175.095 h1.78
  text "A" at 480.341,175.095 h1.78
  text "B" at -14.579,114.643 h1.78
  text "B" at 480.341,114.643 h1.78
  text "C" at -14.579,54.318 h1.78
  text "C" at 480.341,54.318 h1.78
  text "PROJECT TITLE:" at 403.125,7.048 h1.14
  text ".PRJ_Title" at 404.395,3.662 h1.78
  text "DESIGNED FOR:" at 403.125,-0.597 h1.14
  text ".PRJ_Customer" at 404.395,-4.153 h1.78
  text "D" at -14.579,-5.88 h1.78
  text "D" at 361.341,-5.88 h1.78
  text "FILE NAME:" at 403.125,-8.217 h1.14
  text ".PCB_File_Name_No_Path" at 404.395,-11.265 h1.78
  text "Texas Instruments (TI) and/or its licensors do not warrant the accuracy or completeness of this specification" at 157.9,-15.376 h1.14
  text "ENGINEER:" at 403.125,-15.583 h1.14
  text "LAYOUT BY:" at 441.352,-15.583 h1.14
  text "or any information contained therein. TI and/or its licensors do not warrant that this design will meet" at 156.757,-18.237 h1.14
  text ".PRJ_Engineer" at 404.395,-19.52 h1.78
  text ".PCB_Layout" at 442.635,-19.52 h1.78
  text "the specifications, will be suitable for your application or fit for any particular purpose, or will operate in" at 156.757,-21.099 h1.14
  text ".Layer_Name" at 10.656,-21.806 h1.52
  text "ALTIUM DESIGNER VERSION:" at 441.352,-23.457 h1.14
  text "an implementation. TI and/or its licensors do not warrant that the design is production worthy. You should" at 156.757,-23.961 h1.14
  text "completely validate and test your design implementation to confirm the system functionality for your application." at 157.9,-26.822 h1.14
  text ".print_Scale" at 404.395,-26.843 h1.78
  text ".Application_BuildNumber" at 442.635,-26.843 h1.78
  text "1" at 14.792,-32.093 h1.78
  text "2" at 78.182,-32.093 h1.78
  text "3" at 141.411,-32.093 h1.78
  text "4" at 205.08,-32.093 h1.78
  text "5" at 268.555,-32.093 h1.78
  text "6" at 332.182,-32.093 h1.78
M10 Fab Notes:
  drawing of 189 lines, arcs and shapes, not listed
  text ".Layer_Name" at 402.5,165 h1.52
  text "DESIGN INFORMATION" at 429.83,161.911 h1.52
  text "MIN. TRACK WIDTH:" at 413.459,158.555 h1.52
  text "8" at 441.303,158.555 h1.52
  text "MIL" at 445.234,158.555 h1.52
  text "7.874" at 437.077,155.464 h1.52
  text "MIN. CLEARANCE:" at 413.459,155.402 h1.52
  text "MIL" at 445.234,155.402 h1.52
  text "MIN. VIA PAD SIZE:" at 413.459,152.249 h1.52
  text "20" at 440.541,152.249 h1.52
  text "MIL" at 445.234,152.249 h1.52
  text "0.05mm (2MIL)" at 431.112,148.95 h1.52
  text "MINIMUM ANNULAR RING" at 405.096,148.741 h1.52
  text "EXTERNAL" at 449.095,148.741 h1.52
  text "PER" at 410.176,145.944 h1.52
  text "IPC-D-275 CLASS 2 LEVEL C" at 415.764,145.944 h1.52
  text "MIL, HOLES" at 453.565,143.391 h1.52
  text "+/-" at 443.597,143.173 h1.52
  text "+/-" at 465.288,143.173 h1.52
  text "REGISTRATION TOLERANCES:" at 405.096,143.146 h1.52
  text "METAL" at 435.57,143.146 h1.52
  text "5" at 450.206,143.146 h1.52
  text "3" at 471.364,143.146 h1.52
  text "MIL" at 474.317,143.146 h1.52
  text "HOLE SIZE TOLERANCE (UNLESS OTHERWISE SPECIFIED):" at 405.096,140.649 h1.52
  text "+/-" at 465.288,140.576 h1.52
  text "3" at 471.364,140.549 h1.52
  text "MIL" at 474.317,140.549 h1.52
  text "MATERIAL:" at 403.197,137.053 h1.52
  text "FR-4 High Tg" at 428.253,133.788 h1.52
  text "X" at 424.584,133.585 h1.52
  text "FR-4" at 413.891,133.471 h1.52
  text "OTHER" at 451.686,133.471 h1.52
  text "62 MIL (1.6mm) +/-10%" at 422.021,129.838 h1.52
  text "X" at 418.971,129.775 h1.52
  text "THICKNESS:" at 405.096,129.629 h1.52
  text "OTHER" at 454.658,129.629 h1.52
  text "TOLERANCE:" at 405.096,126.116 h1.52
  text "X" at 426.641,126.116 h1.52
  text "ANSI IPC-6012 TYPE 3 CLASS 2" at 431.163,126.116 h1.52
  text "OTHER +/-" at 431.163,122.453 h1.52
  text "BOW & TWIST:" at 405.096,118.766 h1.52
  text "X" at 426.641,118.766 h1.52
  text "ANSI IPC-6012 TYPE 3 CLASS 2" at 431.163,118.766 h1.52
  text "OTHER +/-" at 431.163,115.039 h1.52
  text "DRILLING:" at 403.197,111.722 h1.52
  text "NC_DRILL FILES" at 447.926,109.05 h1.52
  text "REFERENCE:" at 405.096,108.95 h1.52
  text "X" at 421.79,108.947 h1.52
  text "AS SHOWN" at 426.311,108.95 h1.52
  text "X" at 444.675,108.95 h1.52
  text "OTHER" at 455.496,105.337 h1.52
  text "PTH COPPER THICKNESS:" at 405.088,105.247 h1.52
  text "X" at 434.025,105.247 h1.52
  text "20-30 um" at 437.276,105.247 h1.52
  text "BOARD FINISH:" at 403.197,101.498 h1.52
  text "SILKSCREEN:" at 407.14,98.701 h1.52
  text "X" at 431.467,98.701 h1.52
  text "TOP" at 434.439,98.701 h1.52
  text "X" at 444.421,98.701 h1.52
  text "BOTTOM" at 447.418,98.701 h1.52
  text "SILKSCREEN COLOR:" at 407.14,94.759 h1.52
  text "X" at 431.442,94.759 h1.52
  text "WHITE" at 434.439,94.759 h1.52
  text "OTHER" at 447.418,94.759 h1.52
  text "X" at 434.769,91.116 h1.52
  text "GREEN" at 437.766,91.116 h1.52
  text "OTHER" at 453.464,91.116 h1.52
  text "SOLDER RESIST COLOR:" at 407.14,90.941 h1.52
  text "X" at 434.769,87.198 h1.52
  text "MATTE" at 437.766,87.198 h1.52
  text "SEMI-GLOSS" at 453.452,87.181 h1.52
  text "IMMERSION GOLD (ENIG)" at 430.146,82.809 h1.52
  text "ENEPIG" at 464.12,82.626 h1.52
  text "SURFACE FINISH:" at 403.197,82.6 h1.52
  text "X" at 425.625,82.6 h1.52
  text "IMM. TIN/SILVER OR EQUIV" at 411.567,79.113 h1.52
  text "OTHER" at 447.927,79.013 h1.52
  text "ARRAY/PANEL:" at 403.197,75.066 h1.52
  text "CUT AND TRIM PER M1 BOARD OUTLINE" at 430.147,74.857 h1.52
  text "N.C. ROUTE" at 430.146,71.404 h1.52
  text "X" at 447.622,71.404 h1.52
  text "V. SCORE" at 452.143,71.404 h1.52
  text "CERTIFICATION:" at 403.197,68.124 h1.52
  text "MATERIALS AND WORKMANSHIP FOR ALL PCBS" at 421.612,68.124 h1.52
  text "TO MEET OR EXCEED THE REQUIREMENTS OF:" at 421.612,65.735 h1.52
  text "X" at 412.405,62.467 h1.52
  text "ANSI IPC-A-600F CLASS ->" at 415.656,62.467 h1.52
  text "X" at 457.515,62.467 h1.52
  text "2" at 460.309,62.467 h1.52
  text "1" at 452.308,62.429 h1.52
  text "3" at 469.301,62.429 h1.52
  text "X" at 433.03,58.716 h1.52
  text "RoHS" at 436.281,58.716 h1.52
  text "OTHER" at 452.648,58.716 h1.52
  text "PER ORDER" at 462.734,58.716 h1.52
  text "ALL BOARDS MUST MEET OR EXCEED UL94-V0 REQUIREMENTS." at 403.897,54.809 h1.52
  text "PCB MUST BEAR THE UL94V-0 UL REGISTERED MATERIAL ID NUMBER" at 403.897,51.861 h1.52
  text "ADDITIONAL REQUIREMENTS:" at 403.197,47.558 h1.52
  text "MICROSECTION:" at 405.096,44.837 h1.52
  text "YES" at 428.102,44.837 h1.52
  text "REQUIRED" at 449.984,41.17 h1.52
  text "BARE BOARD ELEC. TEST:" at 405.096,41.098 h1.52
  text "NONE" at 438.262,41.098 h1.52
  text "X" at 446.987,41.098 h1.52
  text "PER ORDER" at 465.021,41.098 h1.52
  text "XX MIL VIAS REQUIRE NON-CONDUCTIVE FILL AND PLANARIZE" at 409.367,35.892 h1.5
  text "XX MIL VIAS REQUIRE CONDUCTIVE FILL AND PLANARIZE" at 409.57,33.251 h1.52
  text "OUTER XX MIL TRACES REQUIRE 50 OHM SINGLE-ENDED IMPEDANCE" at 409.545,29.101 h1.47
  text "LAYER 2 & 3 (INNER LAYERS) XX MIL WIDE, XX MIL SPACE / TRACES REQUIRE 100 OHM DIFFERENTIAL IMPEDANCE" at 409.342,23.114 h1.52
  text ".Layer_Name" at 10.656,-21.806 h1.52
M11 Gerber Information:
  lines w0.254: -11.417,-23.626 156.223,-23.626 ; -11.417,-18.462 156.274,-18.462 ; -11.417,-13.297 -11.417,-28.791 90.31,-28.791 156.274,-28.791 156.274,-13.297 -11.404,-13.297 -11.404,-28.791 28.614,-28.791 ; 51.194,-28.791 51.194,-13.297 ; 83.376,-18.462 83.376,-13.297 ; 104.712,-18.462 104.712,-13.297 ; 120.511,-28.956 120.511,-23.804
  text "ALL ARTWORK VIEWED FROM TOP SIDE" at -9.804,-16.654 h1.52
  text "BOARD #:" at 53.099,-16.654 h1.52
  text ".PRJ_Number" at 66.955,-16.654 h1.52
  text "REV:" at 88.405,-16.654 h1.52
  text ".PCB_Rev" at 95.809,-16.654 h1.52
  text "SVN REV:" at 109.69,-16.654 h1.52
  text ".VersionControl_RevNumber" at 169.543,-17.154 h1.52
  text "LAYER NAME =" at -9.804,-21.806 h1.52
  text "TID #:" at 53.099,-21.819 h1.52
  text ".TID" at 66.955,-21.819 h1.52
  text "PLOT NAME =" at -9.804,-27.034 h1.52
  text ".plot_File_Name" at 10.656,-27.034 h1.52
  text "GENERATED    :" at 53.15,-27.034 h1.52
  text ".Print_Date" at 75.235,-27.034 h1.52
  text ".Print_Time" at 93.752,-27.034 h1.52
  text "TEXAS INSTRUMENTS" at 125.87,-27.034 h1.52
M12 Stackup:
  drawing of 264 lines, arcs and shapes, not listed
  text ".Layer_Name" at 334.5,165 h1.52
  text "Layer" at 335.818,161.742 h1.52
  text "Name" at 342.196,161.742 h1.52
  text "Material" at 357.713,161.742 h1.52
  text "Thickness" at 368.796,161.742 h1.52
  text "Constant" at 377.9,161.742 h1.52
  text "Board Layer Stack" at 386.326,161.742 h1.52
  text "Top Overlay" at 342.196,158.694 h1.52
  text "Top Solder" at 342.196,155.646 h1.52
  text "Solder Resist" at 357.713,155.646 h1.52
  text "0.40mil" at 368.796,155.646 h1.52
  text "3.5" at 377.9,155.646 h1.52
  text "1" at 335.818,152.598 h1.52
  text "Top Shielding/Sig" at 342.196,152.598 h1.52
  text "2.76mil" at 368.794,152.598 h1.52
  text "Dielectric 1" at 342.196,149.55 h1.52
  text "PP-006" at 357.713,149.55 h1.52
  text "2.80mil" at 368.794,149.55 h1.52
  text "4.1" at 377.9,149.55 h1.52
  text "2" at 335.817,146.502 h1.52
  text "Sig 1" at 342.196,146.502 h1.52
  text "CF-004" at 357.713,146.502 h1.52
  text "1.38mil" at 368.796,146.502 h1.52
  text "Dielectric 2" at 342.196,143.454 h1.52
  text "PP-006" at 357.713,143.454 h1.52
  text "2.80mil" at 368.794,143.454 h1.52
  text "4.1" at 377.9,143.454 h1.52
  text "3" at 335.818,140.406 h1.52
  text "PWR" at 342.196,140.406 h1.52
  text "CF-004" at 357.713,140.406 h1.52
  text "1.38mil" at 368.796,140.406 h1.52
  text "Dielectric 3" at 342.196,137.358 h1.52
  text "FR-4 High Tg" at 357.713,137.358 h1.52
  text "39.50mil" at 368.796,137.358 h1.52
  text "4.8" at 377.9,137.358 h1.52
  text "4" at 335.818,134.31 h1.52
  text "GND" at 342.196,134.31 h1.52
  text "CF-004" at 357.713,134.31 h1.52
  text "1.38mil" at 368.796,134.31 h1.52
  text "Dielectric 4" at 342.196,131.262 h1.52
  text "PP-006" at 357.713,131.262 h1.52
  text "2.80mil" at 368.794,131.262 h1.52
  text "4.1" at 377.9,131.262 h1.52
  text "5" at 335.818,128.214 h1.52
  text "Sig 4" at 342.196,128.214 h1.52
  text "CF-004" at 357.713,128.214 h1.52
  text "1.38mil" at 368.796,128.214 h1.52
  text "Dielectric 5" at 342.196,125.166 h1.52
  text "PP-006" at 357.713,125.166 h1.52
  text "2.80mil" at 368.794,125.166 h1.52
  text "4.1" at 377.9,125.166 h1.52
  text "6" at 335.818,122.118 h1.52
  text "Bottom Shielding/Sig" at 342.196,122.118 h1.52
  text "2.76mil" at 368.794,122.118 h1.52
  text "Bottom Solder" at 342.196,119.07 h1.52
  text "Solder Resist" at 357.713,119.07 h1.52
  text "0.40mil" at 368.796,119.07 h1.52
  text "3.5" at 377.9,119.07 h1.52
  text "Bottom Overlay" at 342.196,116.022 h1.52
  text ".Layer_Name" at 10.656,-21.806 h1.52
M13 Component Bodies Top:
  text ".Layer_Name" at 10.656,-21.806 h1.52
M14 Component Bodies Bottom:
  text ".Layer_Name" at 10.656,-21.806 h1.52
M15 Courtyards Top:
  text ".Layer_Name" at 10.656,-21.806 h1.52
M16 Courtyards Bottom:
  text ".Layer_Name" at 10.656,-21.806 h1.52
